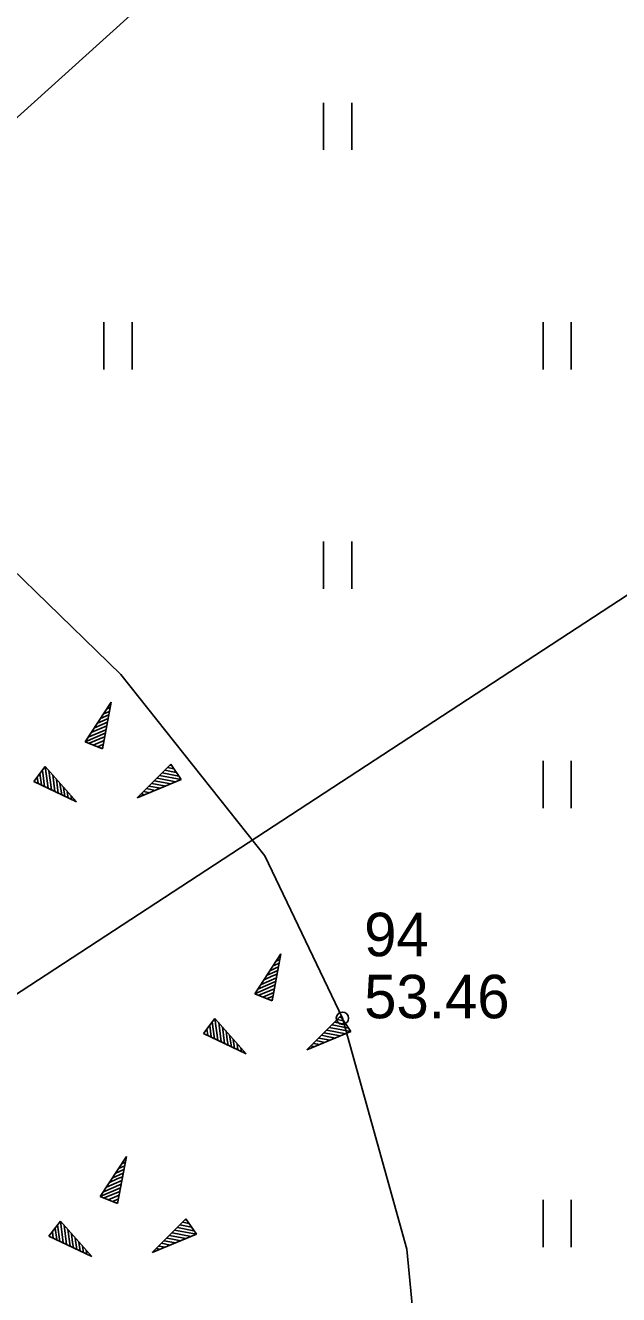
# Model space of a CAD drawing. Extents: x 538599 to 541973, y 6559689 to 6564516.
# Drawn here: x 540583.02 to 540592.57, y 6561313.83 to 6561334.28 of the extents above; entities that cross this region are included whole.
import ezdxf

# ---------------------------------------------------------------- set-up
doc = ezdxf.new("R2010")
doc.units = 0
for name, color, linetype in [('HALJASTUS', 7, 'Continuous'), ('KORGUS-EH2000', 7, 'Continuous'), ('MOOTKORG-EH2000', 7, 'Continuous'), ('MOOTMPUNKT', 7, 'Continuous'), ('MOOTNR', 7, 'Continuous'), ('MOOTPIIR', 7, 'Continuous'), ('PIIR', 7, 'Continuous'), ('RELJEEF', 7, 'Continuous')]:
    doc.layers.add(name, color=color, linetype=linetype)

msp = doc.modelspace()

# ---------------------------------------------------------------- linework, layer by layer
at = {"layer": 'HALJASTUS'}
for p, q in [((540587.818, 6561333.033), (540587.818, 6561332.272)), ((540588.274, 6561333.033), (540588.274, 6561332.272)), ((540584.283, 6561329.498), (540584.283, 6561328.737)), ((540584.738, 6561329.498), (540584.738, 6561328.737)), ((540591.354, 6561329.498), (540591.354, 6561328.737)), ((540591.809, 6561329.498), (540591.809, 6561328.737)), ((540587.818, 6561325.962), (540587.818, 6561325.201)), ((540588.274, 6561325.962), (540588.274, 6561325.201)), ((540591.354, 6561322.427), (540591.354, 6561321.666)), ((540591.809, 6561322.427), (540591.809, 6561321.666)), ((540591.354, 6561315.356), (540591.354, 6561314.595)), ((540591.809, 6561315.356), (540591.809, 6561314.595))]:
    msp.add_line(p, q, dxfattribs=at)
at = {"layer": 'KORGUS-EH2000'}
msp.add_circle((540588.123, 6561318.281), 0.1, dxfattribs=at)
at = {"layer": 'MOOTMPUNKT'}
msp.add_circle((540588.123, 6561318.281), 0.1, dxfattribs=at)
at = {"layer": 'MOOTPIIR'}
msp.add_lwpolyline([(540611.814, 6561347.628), (540600.551, 6561344.045), (540588.991, 6561338.307), (540579.507, 6561329.749), (540567.369, 6561324.711), (540557.296, 6561315.504), (540537.549, 6561303.29), (540525.23, 6561316.048), (540500.22, 6561345.282), (540476.488, 6561371.995), (540449.028, 6561405.277), (540428.792, 6561428.292), (540413.022, 6561448.218), (540405.096, 6561459.889), (540393.809, 6561473.145)], dxfattribs=at)
at = {"layer": 'PIIR'}
for points in [[(540501.31, 6561330.86), (540569.6, 6561385.93), (540606.26, 6561333.96), (540535.92, 6561287.97)], [(540535.92, 6561287.97), (540606.26, 6561333.96), (540640.63, 6561283.66), (540573.77, 6561238.75)]]:
    msp.add_lwpolyline(points, close=True, dxfattribs=at)
at = {"layer": 'RELJEEF'}
for p, q in [((540583.98, 6561322.736), (540584.4, 6561323.376)), ((540584.4, 6561323.376), (540584.26, 6561322.621)), ((540584.375, 6561323.336), (540584.395, 6561323.346)), ((540584.18, 6561323.036), (540584.35, 6561323.111)), ((540584.23, 6561323.111), (540584.36, 6561323.171)), ((540584.275, 6561323.186), (540584.375, 6561323.226)), ((540584.325, 6561323.261), (540584.385, 6561323.286)), ((540584.03, 6561322.811), (540584.315, 6561322.931)), ((540584.08, 6561322.886), (540584.33, 6561322.991)), ((540584.13, 6561322.961), (540584.255, 6561323.016)), ((540584.255, 6561323.016), (540584.34, 6561323.051)), ((540583.98, 6561322.736), (540584.305, 6561322.876)), ((540583.98, 6561322.736), (540584.26, 6561322.621)), ((540584.045, 6561322.711), (540584.295, 6561322.816)), ((540584.11, 6561322.681), (540584.285, 6561322.756)), ((540584.18, 6561322.656), (540584.275, 6561322.696)), ((540584.245, 6561322.631), (540584.26, 6561322.636)), ((540583.338, 6561322.336), (540583.153, 6561322.096)), ((540583.293, 6561322.281), (540583.328, 6561322.011)), ((540583.338, 6561322.336), (540583.843, 6561321.766)), ((540583.338, 6561322.336), (540583.383, 6561321.986)), ((540583.398, 6561322.271), (540583.438, 6561321.961)), ((540584.818, 6561321.831), (540585.358, 6561322.376)), ((540585.448, 6561322.241), (540585.263, 6561322.276)), ((540585.408, 6561322.301), (540585.308, 6561322.321)), ((540585.368, 6561322.361), (540585.348, 6561322.361)), ((540585.528, 6561322.126), (540585.358, 6561322.376)), ((540583.843, 6561321.766), (540583.153, 6561322.096)), ((540583.163, 6561322.111), (540583.168, 6561322.091)), ((540583.208, 6561322.166), (540583.223, 6561322.066)), ((540583.253, 6561322.226), (540583.278, 6561322.041)), ((540583.458, 6561322.201), (540583.493, 6561321.936)), ((540583.518, 6561322.136), (540583.533, 6561321.996)), ((540583.573, 6561322.066), (540583.603, 6561321.881)), ((540585.528, 6561322.126), (540584.818, 6561321.831)), ((540585.143, 6561322.046), (540585.053, 6561322.066)), ((540585.358, 6561322.056), (540585.093, 6561322.106)), ((540585.443, 6561322.091), (540585.138, 6561322.151)), ((540585.528, 6561322.126), (540585.178, 6561322.191)), ((540585.488, 6561322.181), (540585.223, 6561322.236)), ((540583.533, 6561321.996), (540583.548, 6561321.906)), ((540583.633, 6561322.001), (540583.653, 6561321.856)), ((540583.693, 6561321.931), (540583.708, 6561321.831)), ((540583.753, 6561321.866), (540583.763, 6561321.801)), ((540584.943, 6561321.881), (540584.883, 6561321.896)), ((540585.028, 6561321.916), (540584.923, 6561321.936)), ((540585.108, 6561321.951), (540584.968, 6561321.981)), ((540585.193, 6561321.986), (540585.008, 6561322.021)), ((540585.278, 6561322.021), (540585.143, 6561322.046)), ((540583.813, 6561321.796), (540583.818, 6561321.776)), ((540584.858, 6561321.846), (540584.843, 6561321.851)), ((540586.713, 6561318.677), (540587.133, 6561319.317)), ((540587.133, 6561319.317), (540586.993, 6561318.562)), ((540587.058, 6561319.202), (540587.118, 6561319.227)), ((540587.108, 6561319.277), (540587.128, 6561319.287)), ((540586.913, 6561318.977), (540587.083, 6561319.052)), ((540586.963, 6561319.052), (540587.093, 6561319.112)), ((540587.008, 6561319.127), (540587.108, 6561319.167)), ((540586.713, 6561318.677), (540587.038, 6561318.817)), ((540586.763, 6561318.752), (540587.048, 6561318.872)), ((540586.813, 6561318.827), (540587.063, 6561318.932)), ((540586.863, 6561318.902), (540586.988, 6561318.957)), ((540586.988, 6561318.957), (540587.073, 6561318.992)), ((540586.713, 6561318.677), (540586.993, 6561318.562)), ((540586.778, 6561318.652), (540587.028, 6561318.757)), ((540586.843, 6561318.622), (540587.018, 6561318.697)), ((540586.913, 6561318.597), (540587.008, 6561318.637)), ((540586.978, 6561318.572), (540586.993, 6561318.577)), ((540586.071, 6561318.276), (540585.886, 6561318.036)), ((540586.026, 6561318.221), (540586.061, 6561317.951)), ((540586.071, 6561318.276), (540586.576, 6561317.706)), ((540586.071, 6561318.276), (540586.116, 6561317.926)), ((540586.131, 6561318.211), (540586.171, 6561317.901)), ((540587.551, 6561317.771), (540588.091, 6561318.316)), ((540588.181, 6561318.181), (540587.996, 6561318.216)), ((540588.141, 6561318.241), (540588.041, 6561318.261)), ((540588.101, 6561318.301), (540588.081, 6561318.301)), ((540588.261, 6561318.066), (540588.091, 6561318.316)), ((540586.576, 6561317.706), (540585.886, 6561318.036)), ((540585.896, 6561318.051), (540585.901, 6561318.031)), ((540585.941, 6561318.106), (540585.956, 6561318.006)), ((540585.986, 6561318.166), (540586.011, 6561317.981)), ((540586.191, 6561318.141), (540586.226, 6561317.876)), ((540586.251, 6561318.076), (540586.266, 6561317.936)), ((540586.306, 6561318.006), (540586.336, 6561317.821)), ((540588.261, 6561318.066), (540587.551, 6561317.771)), ((540587.876, 6561317.986), (540587.786, 6561318.006)), ((540588.091, 6561317.996), (540587.826, 6561318.046)), ((540588.176, 6561318.031), (540587.871, 6561318.091)), ((540588.011, 6561317.961), (540587.876, 6561317.986)), ((540588.261, 6561318.066), (540587.911, 6561318.131)), ((540588.221, 6561318.121), (540587.956, 6561318.176)), ((540586.266, 6561317.936), (540586.281, 6561317.846)), ((540586.366, 6561317.941), (540586.386, 6561317.796)), ((540586.426, 6561317.871), (540586.441, 6561317.771)), ((540586.486, 6561317.806), (540586.496, 6561317.741)), ((540587.591, 6561317.786), (540587.576, 6561317.791)), ((540587.676, 6561317.821), (540587.616, 6561317.836)), ((540587.761, 6561317.856), (540587.656, 6561317.876)), ((540587.841, 6561317.891), (540587.701, 6561317.921)), ((540587.926, 6561317.926), (540587.741, 6561317.961)), ((540586.546, 6561317.736), (540586.551, 6561317.716)), ((540584.224, 6561315.411), (540584.644, 6561316.051)), ((540584.644, 6561316.051), (540584.504, 6561315.296)), ((540584.569, 6561315.936), (540584.629, 6561315.961)), ((540584.619, 6561316.011), (540584.639, 6561316.021)), ((540584.424, 6561315.711), (540584.594, 6561315.786)), ((540584.474, 6561315.786), (540584.604, 6561315.846)), ((540584.499, 6561315.691), (540584.584, 6561315.726)), ((540584.519, 6561315.861), (540584.619, 6561315.901)), ((540584.224, 6561315.411), (540584.549, 6561315.551)), ((540584.274, 6561315.486), (540584.559, 6561315.606)), ((540584.324, 6561315.561), (540584.574, 6561315.666)), ((540584.374, 6561315.636), (540584.499, 6561315.691)), ((540584.224, 6561315.411), (540584.504, 6561315.296)), ((540584.289, 6561315.386), (540584.539, 6561315.491)), ((540584.354, 6561315.356), (540584.529, 6561315.431)), ((540584.424, 6561315.331), (540584.519, 6561315.371)), ((540584.489, 6561315.306), (540584.504, 6561315.311)), ((540583.583, 6561315.01), (540583.398, 6561314.77)), ((540583.538, 6561314.955), (540583.573, 6561314.685)), ((540583.583, 6561315.01), (540584.088, 6561314.44)), ((540583.583, 6561315.01), (540583.628, 6561314.66)), ((540583.643, 6561314.945), (540583.683, 6561314.635)), ((540585.062, 6561314.505), (540585.602, 6561315.05)), ((540585.732, 6561314.855), (540585.467, 6561314.91)), ((540585.692, 6561314.915), (540585.507, 6561314.95)), ((540585.652, 6561314.975), (540585.552, 6561314.995)), ((540585.612, 6561315.035), (540585.592, 6561315.035)), ((540585.772, 6561314.8), (540585.602, 6561315.05)), ((540584.088, 6561314.44), (540583.398, 6561314.77)), ((540583.408, 6561314.785), (540583.413, 6561314.765)), ((540583.453, 6561314.84), (540583.468, 6561314.74)), ((540583.498, 6561314.9), (540583.523, 6561314.715)), ((540583.703, 6561314.875), (540583.738, 6561314.61)), ((540583.763, 6561314.81), (540583.778, 6561314.67)), ((540583.818, 6561314.74), (540583.848, 6561314.555)), ((540585.772, 6561314.8), (540585.062, 6561314.505)), ((540585.387, 6561314.72), (540585.297, 6561314.74)), ((540585.602, 6561314.73), (540585.337, 6561314.78)), ((540585.687, 6561314.765), (540585.382, 6561314.825)), ((540585.522, 6561314.695), (540585.387, 6561314.72)), ((540585.772, 6561314.8), (540585.422, 6561314.865)), ((540583.778, 6561314.67), (540583.793, 6561314.58)), ((540583.878, 6561314.675), (540583.898, 6561314.53)), ((540583.938, 6561314.605), (540583.953, 6561314.505)), ((540583.998, 6561314.54), (540584.008, 6561314.475)), ((540585.102, 6561314.52), (540585.087, 6561314.525)), ((540585.187, 6561314.555), (540585.127, 6561314.57)), ((540585.272, 6561314.59), (540585.167, 6561314.61)), ((540585.352, 6561314.625), (540585.212, 6561314.655)), ((540585.437, 6561314.66), (540585.252, 6561314.695)), ((540584.058, 6561314.47), (540584.063, 6561314.45))]:
    msp.add_line(p, q, dxfattribs=at)
msp.add_lwpolyline([(540589.422, 6561307.792), (540589.68, 6561309.123), (540589.163, 6561314.56), (540588.123, 6561318.281), (540586.874, 6561320.9), (540584.555, 6561323.82), (540581.615, 6561326.678), (540579.576, 6561326.947), (540575.031, 6561326.471), (540570.87, 6561324.462), (540568.551, 6561322.069), (540567.391, 6561319.222), (540568.551, 6561316.219), (540571.622, 6561311.338), (540573.345, 6561309.041), (540578.266, 6561303.19), (540579.463, 6561302.544), (540580.81, 6561302.787), (540585.578, 6561304.743), (540588.479, 6561306.571), (540589.422, 6561307.792)], dxfattribs=at)

# ---------------------------------------------------------------- texts
at = {"layer": 'KORGUS-EH2000'}
msp.add_text('53.46', height=0.7, dxfattribs=at).set_placement((540588.473, 6561318.281))
at = {"layer": 'MOOTKORG-EH2000'}
msp.add_text('53.46', height=0.7, dxfattribs=at).set_placement((540588.473, 6561318.281))
at = {"layer": 'MOOTNR'}
msp.add_text('94', height=0.7, dxfattribs=at).set_placement((540588.473, 6561319.281))

doc.saveas('drawing.dxf')
